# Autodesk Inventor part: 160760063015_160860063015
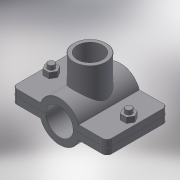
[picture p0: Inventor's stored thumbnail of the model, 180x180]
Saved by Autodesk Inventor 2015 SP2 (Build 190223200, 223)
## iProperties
Created: 2017-05
Part Number: 160760063015_160860063015
Material: Generic
Description: PLASSON SADDLE 63-1.1/2"
Document SubType Name: Modeling
Designer: KIM
Density: 1 g/cm^3
Appearance: Default
Author: KIM
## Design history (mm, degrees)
derived "16076.ipt"
feature "Solid1::16076.ipt"
feature "Solid2::16076.ipt"
tag "TaggingFeature1"
body "Solid1"
other parameters: "d0" = 78.75, "d1" = 116, "d2" = 31.5, "d3" = 63, "d4" = 84, "d5" = 0, "d6" = 5.8, "d7" = 116, "d8" = 0.1, "d10" = 0, "d11" = 0.63, "d14" = 58.2985, "d20" = 0.63, "d23" = 0.63, "d37" = 8, "d38" = 39.5, "d39" = 0, "d40" = 3, "d41" = 5, "d42" = 0, "d43" = 6, "d44" = 3, "d45" = 0, "d46" = 0.63, "d51" = 67, "d52" = 44.845, "d53" = 25, "d54" = 0, "d55" = 39, "d57" = 0, "d58" = 68.04, "d60" = 0, "d63" = 8, "d66" = 68, "d_" = 63, "B_" = 39, "G_" = 44.845, "A_" = 67, "L_" = 116, "L_1" = 84, "l_2" = 25
